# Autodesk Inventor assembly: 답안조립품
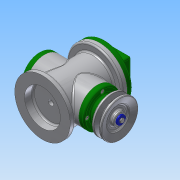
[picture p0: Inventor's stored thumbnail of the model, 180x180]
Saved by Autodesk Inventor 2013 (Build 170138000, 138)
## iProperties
Created: 2018-02
Part Number: 답안조립품
Document SubType Name: Assembly
Designer: Administrator
Author: Administrator
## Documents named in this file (18)
- C:\Users\Administrator\Desktop\480208V1015\답안조립품.iam
- C:\Users\Administrator\Desktop\480208V1015\본체.ipt
- C:\Users\Administrator\Desktop\480208V1015\E-링.ipt
- C:\Users\Administrator\Desktop\480208V1015\V-벨트풀리.ipt
- C:\Users\Administrator\Desktop\480208V1015\덮개.ipt
- C:\Users\Administrator\Desktop\480208V1015\뒤커버.ipt
- C:\Users\Administrator\Desktop\480208V1015\링크.ipt
- C:\Users\Administrator\Desktop\480208V1015\베어링 17 x 40 x 12.ipt
- C:\Users\Administrator\Desktop\480208V1015\볼트 M4 x 8.ipt
- C:\Users\Administrator\Desktop\480208V1015\볼트 M4 x 10.ipt
- C:\Users\Administrator\Desktop\480208V1015\슬라이더.ipt
- C:\Users\Administrator\Desktop\480208V1015\앞커버.ipt
- C:\Users\Administrator\Desktop\480208V1015\오일 실 17 30 8.ipt
- C:\Users\Administrator\Desktop\480208V1015\와셔 4x16.ipt
- C:\Users\Administrator\Desktop\480208V1015\클레비스 핀 6 x 22.ipt
- 클레비스 핀 6 x 22.ipt
- C:\Users\Administrator\Desktop\480208V1015\키 4 x 4 x 12.ipt
- C:\Users\Administrator\Desktop\480208V1015\편심축.ipt
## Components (2 placed, 2 different names)
1. E-링:1
2. V-벨트풀리:1
